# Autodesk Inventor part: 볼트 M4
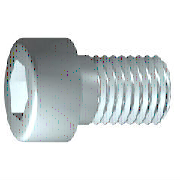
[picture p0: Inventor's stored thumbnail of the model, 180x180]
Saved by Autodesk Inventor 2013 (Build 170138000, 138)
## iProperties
IsCustomPart: 1
Created: 2012-02
Part Number: 볼트 M4
Material: 강철, 연강
Description: 6각머리 태핑 나사
Document SubType Name: Modeling
Standard: KS B 1003
Designer: mduedu
Standards Organization: KS
Language: ko-KR
Size Designation: M 4 x 10
Categories: <MemberInstance><Categories><Category DisplayName="조임쇠" InternalName="e4da775c-781d-43d5-af7c-5136215cf5a6" Mnemonic="FSTN"><Category DisplayName="볼트" InternalN
Density: 1 g/cm^3
Author: mduedu
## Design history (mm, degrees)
sketch "스케치1"
  geometry: L1 (-1, 0)-(10, 0); L2 (10, 0)-(10, 2); L3 (10, 2)-(1.75, 2); L4 (1.75, 2)-(1.32, 2); L5 (1.32, 2)-(0, 2); L6 (0, 2)-(0, 3.5); L7 (0, 3.5)-(-4, 3.5); L8 (-4, 3.5)-(-4, 1.732); L9 (-4, 1.732)-(-2, 1.732); L10 (-2, 1.732)-(-1, 0); L11 (-6.8, 0)-(12.8, 0) reference; L12 (0, -0.7)-(0, 4.2) reference; L13 (1.75, 2)-(0, 2)
  constraints: 22 end point, 6 parallel, 2 collinear, 2 perpendicular, 1 horizontal, 1 point on line
  dimensions: "d1" = 8.25 distance from line of L3.end L2 (= GEL); "d2" = 0.42952 distance of L4.end L3.end (computed from GAL); "d3" = 4 distance between parallel lines of L8 L6 (= KOH); "d4" = 2 distance of L8.end L9.end (= INTI); "d5" = 60 deg angle of L10 L1; "d6" = 4 diameter of L3 L1 (= GD); "d7" = 4 diameter of L5 L1 (= BDM); "d8" = 3.4641 diameter of L9 L1 (= 1.1547 x SW); "d9" = 7 diameter of L7 L1 (= KOD); "d26" = 10 distance between parallel lines of L12 L2 (= NLG)
revolve "본체" sketch "스케치1" stored, may be unused: angle "d10" = 90 deg
sketch "스케치2"
  geometry: L1 (0, -4.9)-(0, 4.9) reference; L2 (-4.9, 0)-(4.9, 0) reference; L3 (1.732, 0)-(0.866, -1.5); L4 (0.866, -1.5)-(-0.866, -1.5); L5 (-0.866, -1.5)-(-1.732, 0); L6 (-1.732, 0)-(-0.866, 1.5); L7 (-0.866, 1.5)-(0.866, 1.5); L8 (0.866, 1.5)-(1.732, 0); 2 further points
  constraints: 12 end point, 1 coincident, 1 horizontal alignment, 1 point on line, 12 other
extrude "슬롯" join sketch "스케치2" stored distance "d11" = 10; taper "d12" = 0 deg
workplane "Work Plane1"
body "Solid1"
fillet "모깎기1" dims "d17" = 0.4 (= RR)
feature "스레드" dims "d13" = 8.25 (= GEL), "d14" = 0
chamfer "모따기1" distance "d15" = 0.42941 (= -0.5 x SPD + 0.5 x GD); stored, may be unused: second distance "d16" = 0.42941 (= GUL), angle "d27" = 45 deg
other parameters: "GD" = 4 (= NND) [user parameter; used in 2 equation terms], "NLG" = 10 [user parameter; used in 1 equation term], "GEL" = 8.25 [user parameter; used in 2 equation terms], "KOD" = 7 [user parameter; used in 1 equation term], "KOH" = 4 [user parameter; used in 1 equation term], "INTI" = 2 [user parameter; used in 1 equation term], "GAL" = 0.42941 (= 0.61345 x PTC) [user parameter; used in 1 equation term], "GUL" = 0.42941 (= 0.61345 x PTC) [user parameter; used in 1 equation term], "BDM" = 4 (= NND) [user parameter; used in 1 equation term], "SW" = 3 [user parameter; used in 2 equation terms], "RR" = 0.4 [user parameter; used in 1 equation term], "SPD" = 3.14117 (= NND - 1.2269 x PTC) [user parameter; used in 1 equation term], "d19" = 0, "d28" = 0, "d29" = 0, "R" = 0.1 [user parameter], "PHH" = 0.2 [user parameter], "GD1" = 3.14117 (= THREADDIA - 1.2269 x PTC) [user parameter], "THREADDIA" = 4 [user parameter; used in 1 equation term], "FAWI" = 45 deg [user parameter], "TPU" = 14.28571 (computed from PTC) [user parameter], "PTC" = 0.7 [user parameter; used in 5 equation terms], "NND" = 4 [user parameter; used in 3 equation terms], "TOA" = 30 deg [user parameter], "E0" = 3.465 (= 1.155 x SW) [user parameter]
